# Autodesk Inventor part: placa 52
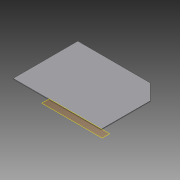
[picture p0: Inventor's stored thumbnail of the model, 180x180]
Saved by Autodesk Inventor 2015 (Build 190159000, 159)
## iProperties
Created: 2015-04
Part Number: placa 52
Material: Generic
Document SubType Name: Modeling
Designer: suporte
Density: 1 g/cm^3
Appearance: Default
Author: suporte
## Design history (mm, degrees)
workplane "Work Plane1"
sketch "Sketch1"
  geometry: L1 (-600, -462.5)-(-600, 62.5) reference; L2 (-600, 62.5)-(-500, 62.5) reference; L3 (-500, 62.5)-(-500, -462.5) reference; L4 (-500, -462.5)-(-600, -462.5) reference; L5 (500, 62.5)-(500, -62.5) reference; L6 (500, -62.5)-(-500, -62.5) reference; L7 (-500, -62.5)-(-500, 62.5) reference; L8 (-500, 62.5)-(500, 62.5) reference; L9 (500, 62.5)-(400, 62.5) reference; L10 (400, 62.5)-(400, 956.058) reference; L11 (400, 956.058)-(500, 856.128) reference; L12 (500, 856.128)-(500, 62.5) reference; L13 (159.763, 1337.5)-(500, 997.5) reference; L14 (500, 997.5)-(500, 856.128) reference; L15 (500, 856.128)-(18.293, 1337.5) reference; L16 (18.293, 1337.5)-(159.763, 1337.5) reference; L17 (118.362, 1237.5)-(-600.237, 1237.5) reference; L18 (-600.237, 1237.5)-(-600.237, 1337.5) reference; L19 (-600.237, 1337.5)-(18.293, 1337.5) reference; L20 (18.293, 1337.5)-(118.362, 1237.5) reference; L21 (-1200, 1337.5)-(-1200, -462.5) reference; L22 (-1200, -462.5)-(-1325, -462.5) reference; L23 (-1325, -462.5)-(-1325, 1337.5) reference; L24 (-1325, 1337.5)-(-1200, 1337.5) reference; L25 (-600.237, 1237.5)-(-1200, 1237.5); L26 (-600, 62.5)-(-1200, 62.5); 1 further point
  constraints: 52 end point, 10 horizontal, 10 vertical, 2 perpendicular, 2 point on line, 24 other
extrude "Extrusion1" new body sketch "Sketch1" distance "d0" = 12.5; taper "d1" = 0 deg
body "Solid1"
